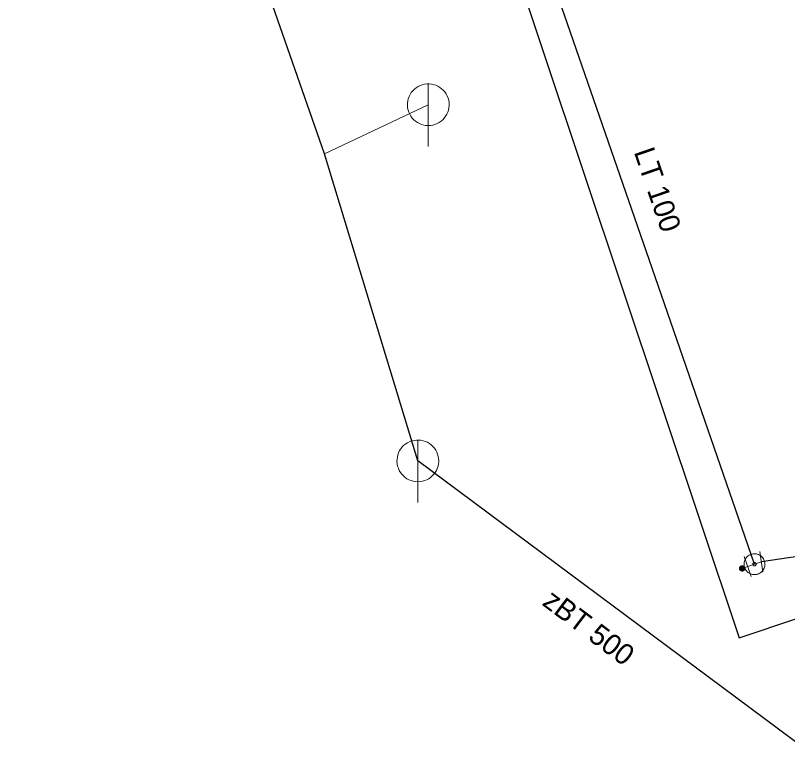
# Model space of a CAD drawing. Extents: x -774415 to -774100, y -975744 to -975502.
# Drawn here: x -774226.39 to -774189.39, y -975685.09 to -975649.01 of the extents above; entities that cross this region are included whole.
import ezdxf

# ---------------------------------------------------------------- set-up
doc = ezdxf.new("R2010")
doc.units = 0
doc.header["$LTSCALE"] = 0.4
doc.linetypes.add('MEDIUM_DASHED', pattern=[4.5, 3, -1.5])
for name, color, linetype, lineweight in [('1', 7, 'MEDIUM_DASHED', 25), ('11', 7, 'Continuous', 13), ('14', 7, 'Continuous', 13), ('17', 7, 'Continuous', 25), ('22', 7, 'Continuous', 13), ('34', 7, 'Continuous', 13), ('47', 7, 'Continuous', 13), ('9', 7, 'Continuous', 13)]:
    doc.layers.add(name, color=color, linetype=linetype, lineweight=lineweight)

msp = doc.modelspace()

# ---------------------------------------------------------------- linework, layer by layer
at = {"layer": '11'}
msp.add_line((-774206.607, -975653.289), (-774211.582, -975655.64), dxfattribs=at)
at = {"layer": '14', "lineweight": 25}
msp.add_line((-774187.309, -975685.09), (-774207.107, -975670.35), dxfattribs=at)
msp.add_lwpolyline([(-774207.107, -975670.35), (-774211.582, -975655.64), (-774220.768, -975629.317)], dxfattribs=at)
at = {"layer": '14'}
msp.add_lwpolyline([(-774190.649, -975675.19), (-774190.98, -975675.3), (-774191.304, -975675.41), (-774191.57, -975675.5)], dxfattribs=at)
at = {"layer": '17'}
for points in [[(-774190.98, -975675.3), (-774195.739, -975661.53), (-774202.46, -975642.109), (-774207.43, -975626.379), (-774211.07, -975615.34), (-774217.71, -975595.969), (-774219.62, -975590.41), (-774224.989, -975576.25), (-774225.51, -975574.5), (-774226.62, -975573.949), (-774228.079, -975573.359), (-774258.14, -975564.129), (-774273.649, -975559.52), (-774289.02, -975554.649), (-774309.699, -975548.23), (-774320.17, -975544.98), (-774321.69, -975541.59), (-774344.199, -975534.469), (-774360.363, -975529.358), (-774373.359, -975525.199), (-774377.583, -975527.43), (-774378.039, -975527.68), (-774378.399, -975527.859), (-774381.76, -975529.64)], [(-774205.166, -975638.503), (-774202.903, -975645.324), (-774191.719, -975678.835), (-774168.992, -975671.211)], [(-774132.516, -975658.154), (-774134.969, -975660.079), (-774158.46, -975678.37), (-774159.14, -975678.219), (-774159.699, -975677.89), (-774166.44, -975671.69), (-774169.59, -975672.079), (-774190.649, -975675.19)]]:
    msp.add_lwpolyline(points, dxfattribs=at)
at = {"layer": '22'}
for p, q in [((-774206.607, -975655.289), (-774206.606, -975652.289)), ((-774207.107, -975672.35), (-774207.106, -975669.35))]:
    msp.add_line(p, q, dxfattribs=at)
for points in [[(-774205.607, -975653.289), (-774205.612, -975653.18), (-774205.63, -975653.072), (-774205.66, -975652.966), (-774205.7, -975652.865), (-774205.752, -975652.768), (-774205.814, -975652.678), (-774205.886, -975652.595), (-774205.966, -975652.521), (-774206.054, -975652.455), (-774206.148, -975652.4), (-774206.248, -975652.355), (-774206.353, -975652.322), (-774206.46, -975652.3), (-774206.569, -975652.29), (-774206.679, -975652.292), (-774206.787, -975652.306), (-774206.894, -975652.331), (-774206.997, -975652.368), (-774207.095, -975652.417), (-774207.187, -975652.475), (-774207.273, -975652.544), (-774207.35, -975652.621), (-774207.419, -975652.707), (-774207.478, -975652.799), (-774207.526, -975652.897), (-774207.563, -975653), (-774207.589, -975653.107), (-774207.603, -975653.215), (-774207.606, -975653.325), (-774207.596, -975653.434), (-774207.575, -975653.541), (-774207.541, -975653.645), (-774207.497, -975653.745), (-774207.442, -975653.84), (-774207.376, -975653.928), (-774207.302, -975654.008), (-774207.219, -975654.08), (-774207.129, -975654.142), (-774207.033, -975654.194), (-774206.931, -975654.235), (-774206.826, -975654.265), (-774206.718, -975654.283), (-774206.608, -975654.289), (-774206.499, -975654.283), (-774206.391, -975654.265), (-774206.286, -975654.236), (-774206.184, -975654.195), (-774206.087, -975654.143), (-774205.997, -975654.081), (-774205.914, -975654.01), (-774205.839, -975653.93), (-774205.774, -975653.842), (-774205.718, -975653.748), (-774205.674, -975653.648), (-774205.64, -975653.544), (-774205.618, -975653.436), (-774205.608, -975653.327)], [(-774206.107, -975670.35), (-774206.112, -975670.241), (-774206.13, -975670.133), (-774206.16, -975670.027), (-774206.2, -975669.926), (-774206.252, -975669.829), (-774206.314, -975669.739), (-774206.386, -975669.656), (-774206.466, -975669.582), (-774206.554, -975669.516), (-774206.648, -975669.461), (-774206.748, -975669.416), (-774206.853, -975669.383), (-774206.96, -975669.361), (-774207.069, -975669.351), (-774207.179, -975669.353), (-774207.287, -975669.367), (-774207.394, -975669.392), (-774207.497, -975669.429), (-774207.595, -975669.478), (-774207.687, -975669.536), (-774207.773, -975669.605), (-774207.85, -975669.682), (-774207.919, -975669.768), (-774207.978, -975669.86), (-774208.026, -975669.958), (-774208.063, -975670.061), (-774208.089, -975670.168), (-774208.103, -975670.276), (-774208.106, -975670.386), (-774208.096, -975670.495), (-774208.075, -975670.602), (-774208.041, -975670.706), (-774207.997, -975670.806), (-774207.942, -975670.901), (-774207.876, -975670.989), (-774207.802, -975671.069), (-774207.719, -975671.141), (-774207.629, -975671.203), (-774207.533, -975671.255), (-774207.431, -975671.296), (-774207.326, -975671.326), (-774207.218, -975671.344), (-774207.108, -975671.35), (-774206.999, -975671.344), (-774206.891, -975671.326), (-774206.786, -975671.297), (-774206.684, -975671.256), (-774206.587, -975671.204), (-774206.497, -975671.142), (-774206.414, -975671.071), (-774206.339, -975670.991), (-774206.274, -975670.903), (-774206.218, -975670.809), (-774206.174, -975670.709), (-774206.14, -975670.605), (-774206.118, -975670.497), (-774206.108, -975670.388)]]:
    msp.add_lwpolyline(points, close=True, dxfattribs=at)
at = {"layer": '34'}
for p, q in [((-774190.575, -975675.684), (-774190.721, -975674.695)), ((-774191.141, -975675.882), (-774191.465, -975674.936))]:
    msp.add_line(p, q, dxfattribs=at)
at = {"layer": '47'}
for points in [[(-774191.143, -975674.827), (-774191.191, -975674.847), (-774191.238, -975674.871), (-774191.28, -975674.901), (-774191.321, -975674.934), (-774191.357, -975674.972), (-774191.389, -975675.014), (-774191.416, -975675.058), (-774191.439, -975675.105), (-774191.457, -975675.154), (-774191.47, -975675.205), (-774191.478, -975675.257), (-774191.479, -975675.309), (-774191.476, -975675.361), (-774191.466, -975675.413), (-774191.452, -975675.463), (-774191.432, -975675.511), (-774191.408, -975675.558), (-774191.378, -975675.601), (-774191.345, -975675.641), (-774191.307, -975675.677), (-774191.265, -975675.709), (-774191.221, -975675.737), (-774191.174, -975675.76), (-774191.125, -975675.778), (-774191.074, -975675.79), (-774191.022, -975675.798), (-774190.97, -975675.8), (-774190.918, -975675.796), (-774190.866, -975675.786), (-774190.816, -975675.772), (-774190.768, -975675.752), (-774190.721, -975675.728), (-774190.677, -975675.699), (-774190.638, -975675.665), (-774190.602, -975675.627), (-774190.569, -975675.586), (-774190.541, -975675.542), (-774190.518, -975675.495), (-774190.501, -975675.445), (-774190.489, -975675.394), (-774190.481, -975675.342), (-774190.479, -975675.29), (-774190.483, -975675.238), (-774190.493, -975675.186), (-774190.507, -975675.136), (-774190.527, -975675.088), (-774190.551, -975675.041), (-774190.58, -975674.998), (-774190.614, -975674.958), (-774190.652, -975674.922), (-774190.693, -975674.889), (-774190.737, -975674.862), (-774190.784, -975674.839), (-774190.834, -975674.822), (-774190.885, -975674.809), (-774190.937, -975674.801), (-774190.988, -975674.8), (-774191.041, -975674.803), (-774191.093, -975674.813)], [(-774191.006, -975675.222), (-774191.015, -975675.225), (-774191.022, -975675.229), (-774191.029, -975675.234), (-774191.035, -975675.239), (-774191.041, -975675.246), (-774191.046, -975675.253), (-774191.051, -975675.26), (-774191.055, -975675.267), (-774191.058, -975675.276), (-774191.06, -975675.284), (-774191.061, -975675.293), (-774191.061, -975675.301), (-774191.061, -975675.31), (-774191.06, -975675.318), (-774191.057, -975675.326), (-774191.054, -975675.335), (-774191.05, -975675.342), (-774191.045, -975675.349), (-774191.04, -975675.355), (-774191.033, -975675.361), (-774191.026, -975675.366), (-774191.019, -975675.371), (-774191.012, -975675.375), (-774191.003, -975675.379), (-774190.995, -975675.38), (-774190.986, -975675.381), (-774190.978, -975675.381), (-774190.969, -975675.381), (-774190.961, -975675.38), (-774190.953, -975675.377), (-774190.944, -975675.374), (-774190.937, -975675.37), (-774190.93, -975675.365), (-774190.924, -975675.36), (-774190.918, -975675.353), (-774190.912, -975675.347), (-774190.908, -975675.339), (-774190.904, -975675.332), (-774190.9, -975675.323), (-774190.899, -975675.315), (-774190.898, -975675.306), (-774190.898, -975675.298), (-774190.898, -975675.289), (-774190.899, -975675.281), (-774190.902, -975675.273), (-774190.905, -975675.264), (-774190.909, -975675.257), (-774190.914, -975675.25), (-774190.919, -975675.244), (-774190.926, -975675.238), (-774190.932, -975675.232), (-774190.94, -975675.228), (-774190.947, -975675.224), (-774190.956, -975675.221), (-774190.964, -975675.219), (-774190.973, -975675.218), (-774190.981, -975675.218), (-774190.99, -975675.218), (-774190.998, -975675.219)]]:
    msp.add_lwpolyline(points, close=True, dxfattribs=at)
at = {"layer": '9'}
for points in [[(-774191.696, -975675.5), (-774191.696, -975675.513), (-774191.693, -975675.526), (-774191.691, -975675.539), (-774191.686, -975675.551), (-774191.679, -975675.563), (-774191.673, -975675.574), (-774191.664, -975675.584), (-774191.654, -975675.594), (-774191.644, -975675.602), (-774191.634, -975675.609), (-774191.622, -975675.615), (-774191.61, -975675.62), (-774191.597, -975675.623), (-774191.583, -975675.625), (-774191.571, -975675.627), (-774191.558, -975675.626), (-774191.544, -975675.624), (-774191.532, -975675.621), (-774191.519, -975675.616), (-774191.507, -975675.61), (-774191.497, -975675.603), (-774191.487, -975675.595), (-774191.477, -975675.585), (-774191.468, -975675.575), (-774191.462, -975675.564), (-774191.456, -975675.552), (-774191.451, -975675.54), (-774191.448, -975675.527), (-774191.446, -975675.514), (-774191.443, -975675.501), (-774191.445, -975675.488), (-774191.446, -975675.475), (-774191.45, -975675.462), (-774191.455, -975675.45), (-774191.46, -975675.438), (-774191.468, -975675.427), (-774191.475, -975675.417), (-774191.485, -975675.407), (-774191.495, -975675.399), (-774191.507, -975675.392), (-774191.519, -975675.386), (-774191.531, -975675.381), (-774191.544, -975675.378), (-774191.556, -975675.376), (-774191.57, -975675.375), (-774191.583, -975675.375), (-774191.595, -975675.377), (-774191.608, -975675.38), (-774191.62, -975675.385), (-774191.632, -975675.391), (-774191.644, -975675.398), (-774191.654, -975675.406), (-774191.664, -975675.416), (-774191.671, -975675.426), (-774191.679, -975675.437), (-774191.684, -975675.449), (-774191.69, -975675.461), (-774191.693, -975675.474), (-774191.695, -975675.487)], [(-774191.676, -975675.5), (-774191.676, -975675.511), (-774191.674, -975675.522), (-774191.671, -975675.533), (-774191.668, -975675.543), (-774191.663, -975675.553), (-774191.657, -975675.562), (-774191.649, -975675.571), (-774191.642, -975675.579), (-774191.632, -975675.586), (-774191.624, -975675.592), (-774191.614, -975675.597), (-774191.603, -975675.601), (-774191.593, -975675.604), (-774191.581, -975675.607), (-774191.571, -975675.607), (-774191.559, -975675.607), (-774191.549, -975675.605), (-774191.538, -975675.602), (-774191.527, -975675.598), (-774191.517, -975675.593), (-774191.509, -975675.587), (-774191.5, -975675.58), (-774191.492, -975675.572), (-774191.485, -975675.563), (-774191.478, -975675.554), (-774191.473, -975675.544), (-774191.47, -975675.534), (-774191.467, -975675.523), (-774191.465, -975675.512), (-774191.463, -975675.501), (-774191.463, -975675.49), (-774191.465, -975675.479), (-774191.468, -975675.468), (-774191.473, -975675.458), (-774191.478, -975675.448), (-774191.483, -975675.439), (-774191.49, -975675.43), (-774191.499, -975675.422), (-774191.507, -975675.415), (-774191.517, -975675.409), (-774191.527, -975675.404), (-774191.536, -975675.4), (-774191.548, -975675.397), (-774191.558, -975675.395), (-774191.57, -975675.395), (-774191.581, -975675.394), (-774191.592, -975675.396), (-774191.603, -975675.399), (-774191.612, -975675.403), (-774191.622, -975675.408), (-774191.632, -975675.414), (-774191.641, -975675.421), (-774191.649, -975675.429), (-774191.656, -975675.438), (-774191.661, -975675.447), (-774191.666, -975675.457), (-774191.671, -975675.467), (-774191.674, -975675.478), (-774191.676, -975675.489)], [(-774191.657, -975675.5), (-774191.657, -975675.509), (-774191.656, -975675.518), (-774191.652, -975675.527), (-774191.649, -975675.535), (-774191.646, -975675.543), (-774191.641, -975675.551), (-774191.634, -975675.558), (-774191.629, -975675.564), (-774191.622, -975675.57), (-774191.614, -975675.575), (-774191.605, -975675.579), (-774191.598, -975675.582), (-774191.588, -975675.585), (-774191.58, -975675.586), (-774191.571, -975675.588), (-774191.561, -975675.587), (-774191.553, -975675.586), (-774191.544, -975675.583), (-774191.536, -975675.58), (-774191.527, -975675.576), (-774191.519, -975675.571), (-774191.512, -975675.565), (-774191.507, -975675.559), (-774191.5, -975675.552), (-774191.495, -975675.544), (-774191.492, -975675.536), (-774191.489, -975675.528), (-774191.485, -975675.519), (-774191.485, -975675.51), (-774191.482, -975675.501), (-774191.483, -975675.492), (-774191.485, -975675.483), (-774191.487, -975675.474), (-774191.49, -975675.466), (-774191.495, -975675.458), (-774191.5, -975675.45), (-774191.505, -975675.443), (-774191.512, -975675.437), (-774191.519, -975675.431), (-774191.527, -975675.426), (-774191.534, -975675.422), (-774191.543, -975675.419), (-774191.551, -975675.416), (-774191.561, -975675.415), (-774191.57, -975675.414), (-774191.578, -975675.414), (-774191.588, -975675.415), (-774191.597, -975675.418), (-774191.605, -975675.421), (-774191.612, -975675.425), (-774191.62, -975675.43), (-774191.627, -975675.436), (-774191.634, -975675.442), (-774191.639, -975675.449), (-774191.644, -975675.457), (-774191.649, -975675.465), (-774191.652, -975675.473), (-774191.654, -975675.482), (-774191.656, -975675.491)], [(-774191.637, -975675.5), (-774191.637, -975675.507), (-774191.636, -975675.514), (-774191.634, -975675.521), (-774191.632, -975675.527), (-774191.629, -975675.533), (-774191.625, -975675.539), (-774191.62, -975675.545), (-774191.615, -975675.55), (-774191.61, -975675.554), (-774191.603, -975675.558), (-774191.598, -975675.561), (-774191.592, -975675.564), (-774191.585, -975675.565), (-774191.578, -975675.568), (-774191.571, -975675.568), (-774191.563, -975675.568), (-774191.556, -975675.566), (-774191.549, -975675.565), (-774191.544, -975675.562), (-774191.536, -975675.559), (-774191.532, -975675.555), (-774191.526, -975675.551), (-774191.521, -975675.546), (-774191.517, -975675.54), (-774191.512, -975675.534), (-774191.509, -975675.528), (-774191.507, -975675.522), (-774191.505, -975675.515), (-774191.504, -975675.508), (-774191.502, -975675.501), (-774191.502, -975675.494), (-774191.504, -975675.487), (-774191.505, -975675.48), (-774191.509, -975675.474), (-774191.512, -975675.467), (-774191.516, -975675.462), (-774191.519, -975675.456), (-774191.524, -975675.451), (-774191.531, -975675.447), (-774191.536, -975675.443), (-774191.543, -975675.44), (-774191.549, -975675.437), (-774191.556, -975675.435), (-774191.563, -975675.434), (-774191.57, -975675.434), (-774191.576, -975675.434), (-774191.583, -975675.434), (-774191.59, -975675.436), (-774191.597, -975675.439), (-774191.603, -975675.442), (-774191.608, -975675.446), (-774191.615, -975675.45), (-774191.62, -975675.455), (-774191.624, -975675.461), (-774191.627, -975675.466), (-774191.63, -975675.473), (-774191.634, -975675.479), (-774191.634, -975675.486), (-774191.637, -975675.493)], [(-774191.617, -975675.5), (-774191.617, -975675.505), (-774191.617, -975675.51), (-774191.615, -975675.515), (-774191.614, -975675.519), (-774191.612, -975675.524), (-774191.608, -975675.528), (-774191.605, -975675.531), (-774191.602, -975675.535), (-774191.598, -975675.538), (-774191.595, -975675.541), (-774191.59, -975675.543), (-774191.585, -975675.545), (-774191.581, -975675.546), (-774191.576, -975675.548), (-774191.571, -975675.548), (-774191.566, -975675.548), (-774191.561, -975675.547), (-774191.556, -975675.546), (-774191.551, -975675.544), (-774191.546, -975675.542), (-774191.543, -975675.539), (-774191.539, -975675.536), (-774191.536, -975675.532), (-774191.532, -975675.529), (-774191.529, -975675.525), (-774191.527, -975675.52), (-774191.526, -975675.516), (-774191.524, -975675.511), (-774191.524, -975675.506), (-774191.522, -975675.501), (-774191.522, -975675.496), (-774191.524, -975675.491), (-774191.524, -975675.486), (-774191.527, -975675.482), (-774191.529, -975675.477), (-774191.532, -975675.473), (-774191.534, -975675.469), (-774191.538, -975675.466), (-774191.541, -975675.463), (-774191.546, -975675.46), (-774191.551, -975675.458), (-774191.554, -975675.456), (-774191.559, -975675.455), (-774191.565, -975675.454), (-774191.57, -975675.454), (-774191.575, -975675.454), (-774191.58, -975675.455), (-774191.585, -975675.455), (-774191.588, -975675.457), (-774191.593, -975675.459), (-774191.598, -975675.462), (-774191.6, -975675.465), (-774191.605, -975675.468), (-774191.607, -975675.472), (-774191.61, -975675.476), (-774191.612, -975675.481), (-774191.615, -975675.485), (-774191.615, -975675.49), (-774191.617, -975675.495)], [(-774191.597, -975675.5), (-774191.597, -975675.503), (-774191.598, -975675.506), (-774191.597, -975675.508), (-774191.595, -975675.511), (-774191.595, -975675.514), (-774191.593, -975675.516), (-774191.59, -975675.518), (-774191.588, -975675.52), (-774191.587, -975675.522), (-774191.585, -975675.524), (-774191.581, -975675.526), (-774191.578, -975675.527), (-774191.576, -975675.527), (-774191.573, -975675.528), (-774191.571, -975675.528), (-774191.568, -975675.528), (-774191.565, -975675.528), (-774191.561, -975675.527), (-774191.559, -975675.526), (-774191.556, -975675.525), (-774191.554, -975675.523), (-774191.551, -975675.521), (-774191.549, -975675.519), (-774191.549, -975675.517), (-774191.546, -975675.515), (-774191.546, -975675.512), (-774191.544, -975675.509), (-774191.544, -975675.507), (-774191.543, -975675.504), (-774191.541, -975675.501), (-774191.543, -975675.498), (-774191.543, -975675.495), (-774191.544, -975675.492), (-774191.544, -975675.49), (-774191.546, -975675.487), (-774191.548, -975675.485), (-774191.549, -975675.482), (-774191.551, -975675.48), (-774191.554, -975675.479), (-774191.556, -975675.477), (-774191.558, -975675.476), (-774191.561, -975675.475), (-774191.563, -975675.474), (-774191.566, -975675.474), (-774191.57, -975675.473), (-774191.573, -975675.474), (-774191.576, -975675.473), (-774191.578, -975675.475), (-774191.581, -975675.475), (-774191.583, -975675.476), (-774191.585, -975675.478), (-774191.588, -975675.479), (-774191.59, -975675.481), (-774191.592, -975675.484), (-774191.593, -975675.486), (-774191.595, -975675.489), (-774191.595, -975675.491), (-774191.597, -975675.494), (-774191.597, -975675.497)], [(-774191.578, -975675.5), (-774191.578, -975675.502), (-774191.578, -975675.502), (-774191.576, -975675.502), (-774191.576, -975675.504), (-774191.578, -975675.505), (-774191.576, -975675.505), (-774191.576, -975675.505), (-774191.576, -975675.507), (-774191.576, -975675.507), (-774191.575, -975675.508), (-774191.573, -975675.508), (-774191.573, -975675.508), (-774191.573, -975675.509), (-774191.571, -975675.509), (-774191.571, -975675.509), (-774191.57, -975675.509), (-774191.568, -975675.509), (-774191.568, -975675.508), (-774191.568, -975675.508), (-774191.566, -975675.508), (-774191.566, -975675.507), (-774191.566, -975675.507), (-774191.565, -975675.506), (-774191.565, -975675.506), (-774191.563, -975675.505), (-774191.563, -975675.504), (-774191.561, -975675.503), (-774191.561, -975675.503), (-774191.561, -975675.502), (-774191.561, -975675.501), (-774191.561, -975675.5), (-774191.561, -975675.499), (-774191.561, -975675.499), (-774191.563, -975675.498), (-774191.563, -975675.497), (-774191.563, -975675.496), (-774191.563, -975675.496), (-774191.565, -975675.495), (-774191.565, -975675.495), (-774191.566, -975675.494), (-774191.566, -975675.494), (-774191.568, -975675.493), (-774191.568, -975675.493), (-774191.568, -975675.493), (-774191.57, -975675.493), (-774191.571, -975675.493), (-774191.571, -975675.493), (-774191.571, -975675.493), (-774191.573, -975675.494), (-774191.573, -975675.493), (-774191.575, -975675.495), (-774191.575, -975675.495), (-774191.576, -975675.495), (-774191.576, -975675.495), (-774191.576, -975675.497), (-774191.576, -975675.498), (-774191.576, -975675.499), (-774191.578, -975675.499), (-774191.578, -975675.5)]]:
    msp.add_lwpolyline(points, close=True, dxfattribs=at)

# ---------------------------------------------------------------- texts
at = {"layer": '1'}
for s, rotation, p in [('LT 100', 289, (-774196.766, -975655.546)), ('zBT 500 ', 323, (-774201.2, -975677.221))]:
    msp.add_text(s, height=1, rotation=rotation, dxfattribs=at).set_placement(p)

doc.saveas('drawing.dxf')
